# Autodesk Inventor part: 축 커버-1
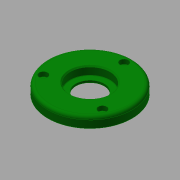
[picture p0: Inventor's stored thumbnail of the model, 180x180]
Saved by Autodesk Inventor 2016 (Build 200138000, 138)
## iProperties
Created: 2015-10
Part Number: 축 커버-1
Document SubType Name: Modeling
Designer: mdu
Density: 7.86 g/cm^3
Material: 강철, 연강
Appearance: 진녹색
Mass: 324.903 g
Surface Area: 132.124 cm^2
Volume: 41.3362 cm^3
Author: mdu
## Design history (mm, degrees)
sketch "스케치1"
  geometry: C1 r 40 at (0, 0) reference; C2 r 26 at (0, 0) reference; 1 further point
  node "참조1"
  node "참조2"
extrude "돌출1" new body sketch "스케치1" distance "d0" = 10; taper "d1" = 0 deg
extrude "돌출2" join sketch "스케치1" distance "d2" = 3; taper "d3" = 0 deg
hole "구멍1" diameter "d6" = 27; stored, may be unused: countersink angle "d10" = 90 deg, drill point angle "d12" = 118 deg; dims "d4" = 10, "d5" = 10, "d7" = 6, "d8" = 38, "d9" = 8, "d11" = 8
sketch "스케치2"
  geometry: C1 r 20 at (0, 0); 1 further point
  constraints: 1 centre point, 1 coincident
  dimensions: "d13" = 40 diameter of C1
extrude "돌출3" cut sketch "스케치2" distance "d14" = 3; taper "d15" = 0 deg
sketch "스케치3"
  geometry: C1 r 1.621 at (0, 32.5) reference; 1 further point
hole "구멍2" sketch "스케치3" at (0, 32.5) diameter "d16" = 4.5; stored, may be unused: countersink angle "d20" = 90 deg, drill point angle "d22" = 118 deg; dims "d17" = 6, "d18" = 8, "d19" = 4.4, "d21" = 8
fillet "모깎기1" dims "d26" = 3, "d27" = 0.3
chamfer "모따기1" distance "d28" = 1; stored, may be unused: second distance "d29" = 2, angle "d30" = 45 deg
node "솔리드1"
pattern_circular "원형 패턴1" dims angle "d24" = 360 deg
node "참조3"
